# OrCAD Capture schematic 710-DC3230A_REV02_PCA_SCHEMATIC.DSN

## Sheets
1 PAGE1: size Custom
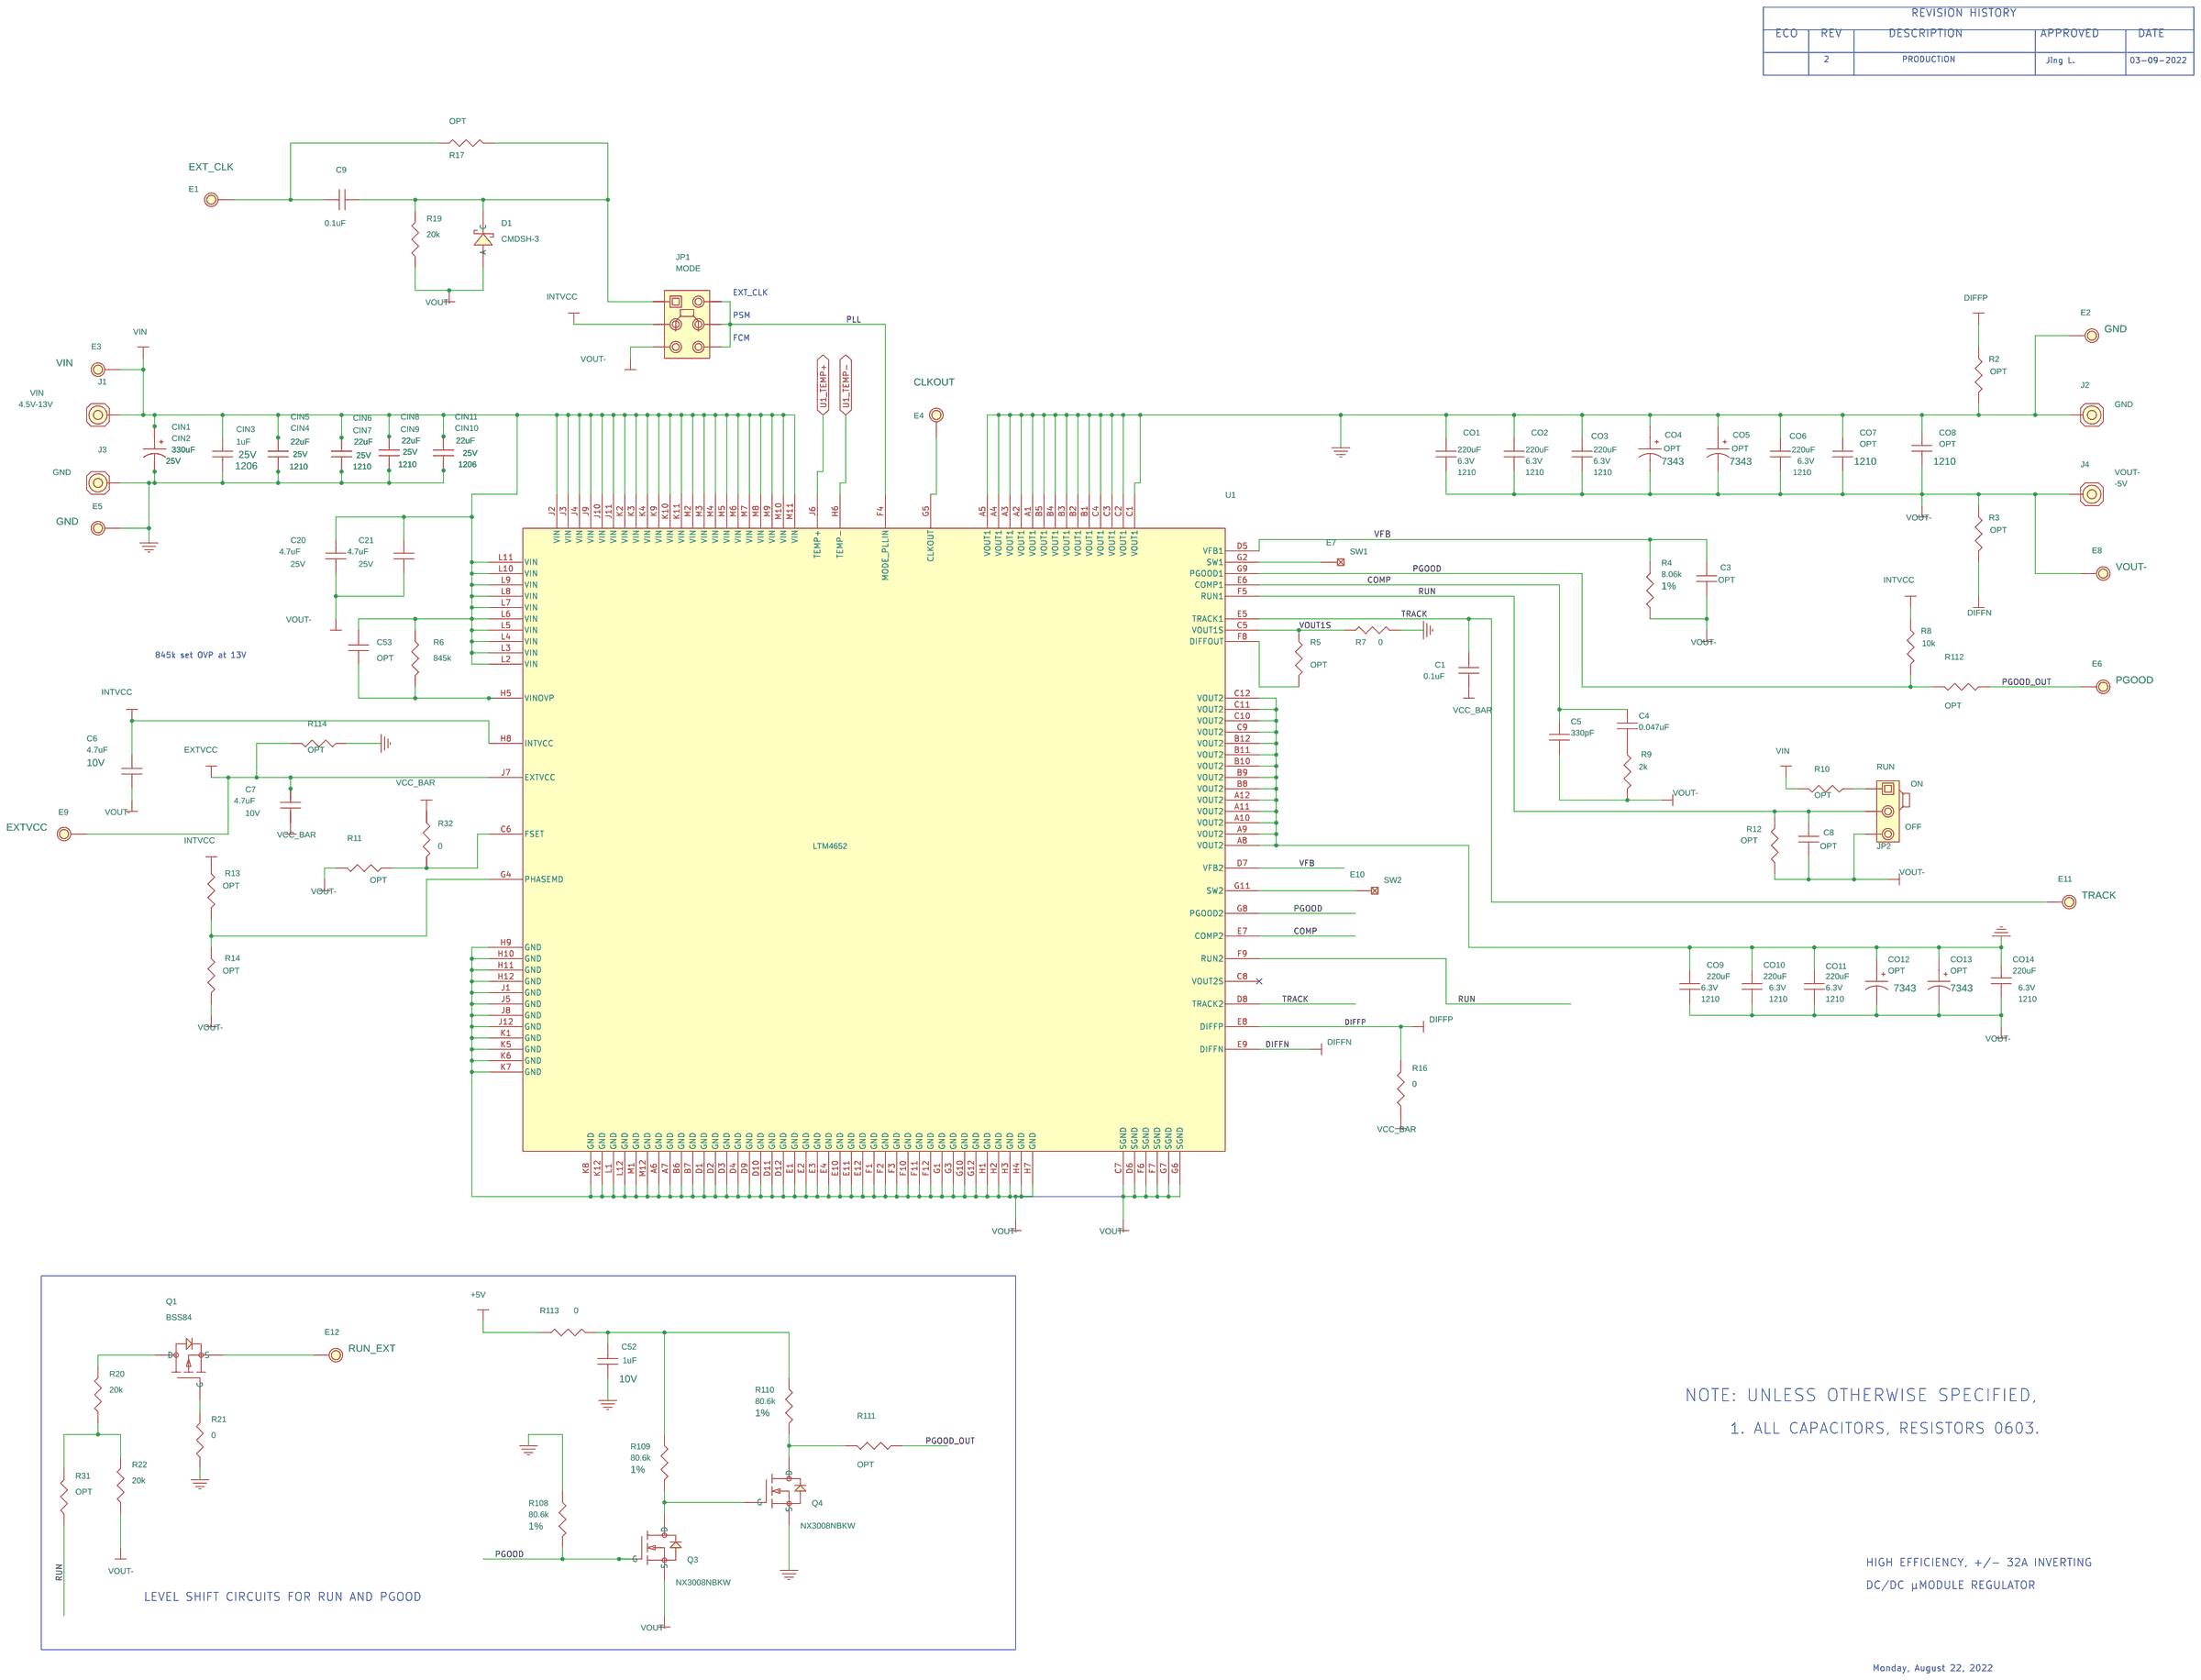
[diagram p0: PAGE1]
2 PAGE2: size Custom
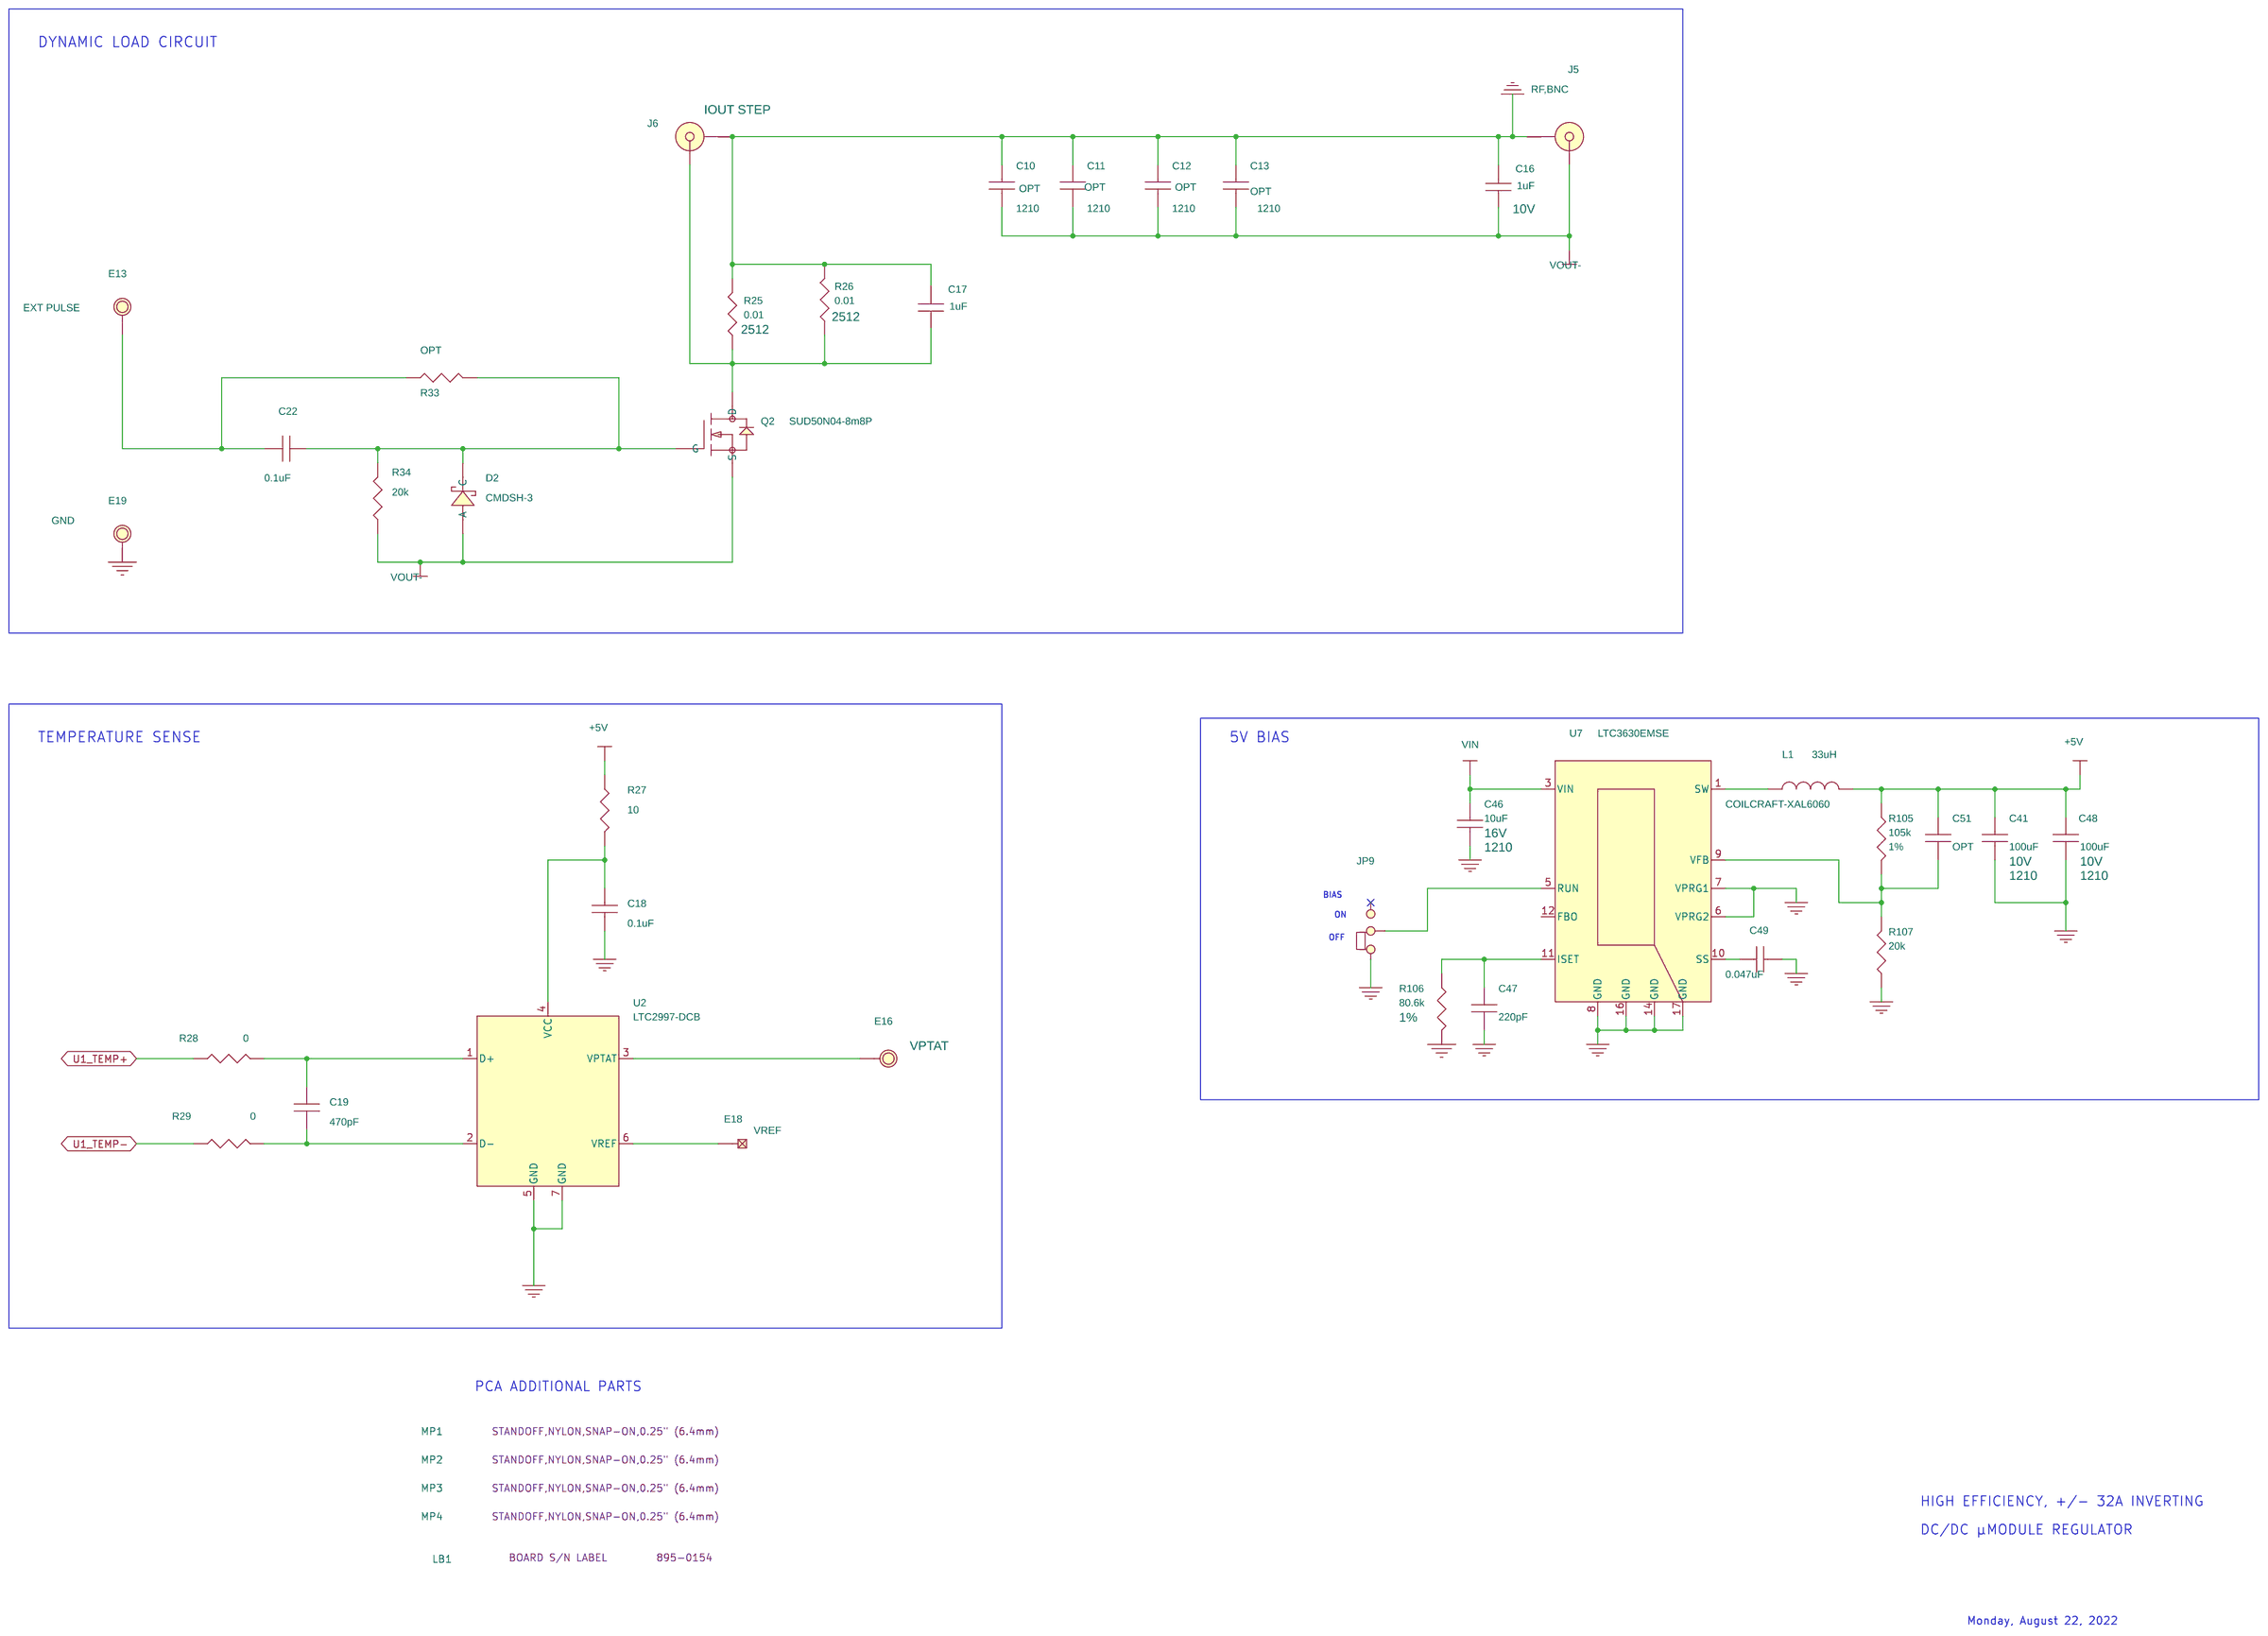
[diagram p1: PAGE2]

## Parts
sheet PAGE1
C1  0.1uF  [CC0603N]
C3  OPT  [CC0603N]
C4  0.047uF  [CC0603N]
C5  330pF  [CC0603N]
C6  4.7uF  [CC0603N]
C7  4.7uF  [CC0603N]
C8  OPT  [CC0603N]
C9  0.1uF  [CC0603N]
C20  4.7uF  [CC0603N]
C21  4.7uF  [CC0603N]
C52  1uF  [CC0603N]
C53  OPT  [CC0603N]
CIN1  330uF  [PANASONIC_ZC_10X10.2]
CIN2  330uF  [PANASONIC_ZC_10X10.2]
CIN3  1uF  [CC1206N]
CIN4  22uF  [CC1210N]
CIN5  22uF  [CC1210N]
CIN6  22uF  [CC1210N]
CIN7  22uF  [CC1210N]
CIN8  22uF  [CC1210N]
CIN9  22uF  [CC1210N]
CIN10  22uF  [CC1206N]
CIN11  22uF  [CC1206N]
CO1  220uF  [CC1210N]
CO2  220uF  [CC1210N]
CO3  220uF  [CC1210N]
CO4  OPT  [CAPMP7343N]
CO5  OPT  [CAPMP7343N]
CO6  220uF  [CC1210N]
CO7  OPT  [CC1210N]
CO8  OPT  [CC1210N]
CO9  220uF  [CC1210N]
CO10  220uF  [CC1210N]
CO11  220uF  [CC1210N]
CO12  OPT  [CAPMP7343N]
CO13  OPT  [CAPMP7343N]
CO14  220uF  [CC1210N]
D1  CMDSH-3  [SOD-323N]
E1  TEST POINT  [MILLMAX2308]
E2  TEST POINT  [MILLMAX2308]
E3  TEST POINT  [MILLMAX2308]
E4  TEST POINT  [MILLMAX2308]
E5  TEST POINT  [MILLMAX2308]
E6  TEST POINT  [MILLMAX2308]
E7  Testpoint  [030\smd]
E8  TEST POINT  [MILLMAX2308]
E9  TEST POINT  [MILLMAX2308]
E10  Testpoint  [030\smd]
E11  TEST POINT  [MILLMAX2308]
E12  TEST POINT  [MILLMAX2308]
J1  STUD,#10-32  [PENN-KFH-032]
J2  STUD,#10-32  [PENN-KFH-032]
J3  STUD,#10-32  [PENN-KFH-032]
J4  STUD,#10-32  [PENN-KFH-032]
JP1  HDR  [HD2X3-079]
JP2  HDR  [HD1X3-079]
Q1  BSS84  [SOT23-3N]
Q3  NX3008NBKW  [SOT323-3N]
Q4  NX3008NBKW  [SOT323-3N]
R2  OPT  [CR0603N]
R3  OPT  [CR0603N]
R4  8.06k  [CR0603N]
R5  OPT  [CR0603N]
R6  845k  [CR0603N]
R7  0  [CR0603N]
R8  10k  [CR0603N]
R9  2k  [CR0603N]
R10  OPT  [CR0603N]
R11  OPT  [CR0603N]
R12  OPT  [CR0603N]
R13  OPT  [CR0603N]
R14  OPT  [CR0603N]
R16  0  [CR0603N]
R17  OPT  [CR0603N]
R19  20k  [CR0603N]
R20  20k  [CR0603N]
R21  0  [CR0603N]
R22  20k  [CR0603N]
R31  OPT  [CR0603N]
R32  0  [CR0603N]
R108  80.6k  [CR0603N]
R109  80.6k  [CR0603N]
R110  80.6k  [CR0603N]
R111  OPT  [CR0603N]
R112  OPT  [CR0603N]
R113  0  [CR0603N]
R114  OPT  [CR0603N]
U1  LTM4652  [LTM-BGA-144-7064]
XJP1  SHUNT
XJP2  SHUNT
sheet PAGE2
C10  OPT  [CC1210N]
C11  OPT  [CC1210N]
C12  OPT  [CC1210N]
C13  OPT  [CC1210N]
C16  1uF  [CC0603N]
C17  1uF  [CC0603N]
C18  0.1uF  [CC0603N]
C19  470pF  [CC0603N]
C22  0.1uF  [CC0603N]
C41  100uF  [CC1210N]
C46  10uF  [CC1210N]
C47  220pF  [CC0603N]
C48  100uF  [CC1210N]
C49  0.047uF  [CC0603N]
C51  OPT  [CC0603N]
D2  CMDSH-3  [SOD-323N]
E13  TEST POINT  [MILLMAX2308]
E16  TEST POINT  [MILLMAX2308]
E18  Testpoint  [030\smd]
E19  TEST POINT  [MILLMAX2308]
J5  RF,BNC  [CONNEX-112404]
J6  RF,BNC  [CONNEX-112404]
JP9  HDR  [HD1X3-079]
L1  33uH  [COILCRAFT-XAL6060]
LB1  LABEL  [895-0154_REV01]
MP1  STANDOFF  [MTG-8831]
MP2  STANDOFF  [MTG-8831]
MP3  STANDOFF  [MTG-8831]
MP4  STANDOFF  [MTG-8831]
Q2  SUD50N04-8m8P  [TO-252-3N]
R25  0.01  [VISHAY-WSL2512_T30]
R26  0.01  [VISHAY-WSL2512_T30]
R27  10  [CR0603N]
R28  0  [CR0603N]
R29  0  [CR0603N]
R33  OPT  [CR0603N]
R34  20k  [CR0603N]
R105  105k  [CR0603N]
R106  80.6k  [CR0603N]
R107  20k  [CR0603N]
U2  LTC2997-DCB  [LTC-DCB-6-1715]
U7  LTC3630EMSE  [LTC-MSE-16-1871]
XJP9  SHUNT

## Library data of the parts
C1 C9 C22 = CAP: CAP.,0.1uF,X7R,25V,10%,0603; CLASS: DISCRETE; Dielectric Type: X7R; FPLIST: CC0603N,CC0603L,CC0603M; Inventory Qty: 60590; Manufacturer: AVX; Manufacturer PN: 06033C104KAT2A; PART_NUMBER: 150-0065; Package Size: 0603; Part Number: AVX 06033C104KAT2A; Rated Voltage: 25V; Tolerance: 10%
C3 C8 C53 = CAP: CAP., OPTION, 0603; 6th Part Field: (OPT); CLASS: DISCRETE; FPLIST: CC0603N,CC0603L,CC0603M; PART_NUMBER: 150-3038; Package Size: 0603; Package Type: SMD; Part Number: OPTION
C4 = CAP: CAP.,0.047uF,X7R,50V,10%,0603; 6th Part Field: 10nF; CLASS: DISCRETE; Dielectric Type: X7R; FPLIST: CC0603N,CC0603L,CC0603M; Inventory Qty: 19580; Manufacturer: AVX; Manufacturer PN: 06035C473KAT2A; PART_NUMBER: 150-0097; Package Size: 0603; Part Number: OPTION; Rated Voltage: 50V; Tolerance: 10%
C5 = CAP: CAP.,330pF,C0G,50V,5%,0603; 6th Part Field: (OPT); CLASS: DISCRETE; Dielectric Type: C0G; FPLIST: CC0603N,CC0603L,CC0603M; Inventory Qty: 11392; Manufacturer: AVX; Manufacturer PN: 06035A331JAT2A; PART_NUMBER: 150-0611; Package Size: 0603; Part Number: OPTION; Rated Voltage: 50V; Tolerance: 5%
C6 = CAP: CAP.,4.7uF,X5R,10V,10%,0603; 1st Part Field: 10V; CLASS: DISCRETE; Dielectric Type: X5R; FPLIST: CC0603N,CC0603L,CC0603M; Inventory Qty: 20774; Manufacturer: AVX; Manufacturer PN: 0603ZD475KAT2A; PART_NUMBER: 150-3050; Package Size: 0603; Part Number: TAIYO YUDEN LMK107BJ225MA; Rated Voltage: 10V; Tolerance: 10%
C7 = CAP: CAP.,4.7uF,X5R,10V,20%,0603; 1st Part Field: 10V; CLASS: DISCRETE; Dielectric Type: X5R; FPLIST: CC0603N,CC0603L,CC0603M; Inventory Qty: 700; Manufacturer: WURTH ELEKTRONIK; Manufacturer PN: 885012106012; PART_NUMBER: 150-0743; Package Size: 0603; Part Number: TAIYO YUDEN LMK107BJ225MA; Rated Voltage: 10V; Tolerance: 20%
C20 C21 = CAP: CAP.,4.7uF,X5R,25V,10%,0603; 1st Part Field: 10V; CLASS: DISCRETE; Dielectric Type: X5R; FPLIST: CC0603N,CC0603L,CC0603M; Inventory Qty: 10846; Manufacturer: MURATA; Manufacturer PN: GRM188R61E475KE15D; PART_NUMBER: 150-0445; Package Size: 0603; Part Number: TAIYO YUDEN LMK107BJ225MA; Rated Voltage: 25V; Tolerance: 10%
C16 C17 C52 = CAP: CAP.,1uF,X7R,10V,10%,0603; CLASS: DISCRETE; Dielectric Type: X7R; FPLIST: CC0603N,CC0603L,CC0603M; Inventory Qty: 56548; Manufacturer: AVX; Manufacturer PN: 0603ZC105KAT2A; PART_NUMBER: 150-3414; Package Size: 0603; Rated Voltage: 10V; Tolerance: 10%
CIN1 CIN2 = CAP_P_ALT: CAP.,330uF,ALUM POLYMER ELEC,25V,20%,SMD,10x10.2mm,AEC-Q200; 1st Part Field: 25V; CLASS: DISCRETE; Dielectric Type: ALUM POLYMER ELEC; FPLIST: PANASONIC_ZC_10X10.2,PANASONIC_ZC_10X10-2; Inventory Qty: 1970; Manufacturer: PANASONIC; Manufacturer PN: EEHZC1E331P; PART_NUMBER: 150-1278; Package Size: SMD,10x10.2mm; Part Number: SUNCON 25CE150AX; Rated Voltage: 25V; Tolerance: 20%
CIN3 = CAP: CAP.,1uF,X7R,25V,10%,1206; 1st Part Field: 25V; CLASS: DISCRETE; Dielectric Type: X7R; FPLIST: CC1206N,CC1206L,CC1206M; Inventory Qty: 22532; Manufacturer: AVX; Manufacturer PN: 12063C105KAT2A; PART_NUMBER: 150-0174; Package Size: 1206; Part Number: TAIYO YUDEN TMK316BJ105KD-T; Rated Voltage: 25V; Tolerance: 10%
CIN4-CIN9 = CAP: CAP.,22uF,X5R,25V,10%,1210,NO SUBS ALLOWED; 1st Part Field: 25V; CLASS: DISCRETE; Dielectric Type: X5R; FPLIST: CC1210N,CC1210L,CC1210M; Inventory Qty: 4000; Manufacturer: MURATA; Manufacturer PN: GRM32ER61E226KE15K; PART_NUMBER: 150-1818; Package Size: 1210; Package Type: SMD; Part Number: AVX 1210D226KAT2A; Rated Voltage: 25V; Tolerance: 10%
CIN10 CIN11 = CAP: CAP.,22uF,X6S,25V,20%,1206; 1st Part Field: 25V; CLASS: DISCRETE; Dielectric Type: X6S; FPLIST: CC1206N,CC1206L,CC1206M; Inventory Qty: 0; Manufacturer: MURATA; Manufacturer PN: GRM31CC81E226ME11L; PART_NUMBER: 150-1811; Package Size: 1206; Part Number: AVX 1210D226KAT2A; Rated Voltage: 25V; Tolerance: 20%
CO1-CO3 CO6 CO10 CO11 CO14 = CAP: CAP.,220uF,X5R,6.3V,20%,1210,NO SUBS ALLOWED; 6th Part Field: (OPT); CLASS: DISCRETE; Dielectric Type: X5R; FPLIST: CC1210L,CC1210N,CC1210M; Inventory Qty: 4000; Manufacturer: MURATA; Manufacturer PN: GRM32ER60J227ME05K; PART_NUMBER: 150-1822; Package Size: 1210; Package Type: Surface Mount, MLCC; Part Number: OPTION; Rated Voltage: 6.3V; Temperature Coefficient: X5R; Tolerance: 20%
CO4 CO5 CO12 CO13 = CAP_P_ALT: CAP., OPTION, 7343; CLASS: DISCRETE; FPLIST: CAPMP7343N,CAPMP7343L,CAPMP7343M; PART_NUMBER: 150-0067; Package Size: 7343; Package Type: SMD; Part Number: SANYO 4TPE470MCL
CO7 CO8 = CAP: CAP., OPTION, 1210; 1st Part Field: 6.3V; CLASS: DISCRETE; FPLIST: CC1210N,CC1210L,CC1210M; PART_NUMBER: 150-3035; Package Size: 1210; Package Type: SMD; Part Number: TAIYO YUDEN LMK325BJ107MM-T
CO9 = CAP: CAP.,220uF,X5R,6.3V,20%,1210,NO SUBS ALLOWED; 1st Part Field: 6.3V; CLASS: DISCRETE; Dielectric Type: X5R; FPLIST: CC1210L,CC1210N,CC1210M; Inventory Qty: 4000; Manufacturer: MURATA; Manufacturer PN: GRM32ER60J227ME05K; PART_NUMBER: 150-1822; Package Size: 1210; Package Type: Surface Mount, MLCC; Part Number: TAIYO YUDEN LMK325BJ107MM-T; Rated Voltage: 6.3V; Temperature Coefficient: X5R; Tolerance: 20%
D1 D2 = DIODE_SCHOTTKY_A: DIODE,SCHOTTKY,30V,250mW, 100mA,SOD-323; CLASS: DISCRETE; FPLIST: SOD-323N,SOD-323L,SOD-323M; Inventory Qty: 7578; Manufacturer: CENTRAL SEMI.; Manufacturer PN: CMDSH-3 TR LEAD FREE; Max Forward Current or Rated Power: 100mA; PART_NUMBER: 210-0081; Package Size: SOD-323; Package Type: SOD-323; Rated Voltage or Zener Voltage: 30V
E1 = TEST_POINT_.156_MILL-MAX_2308_A: TEST POINT,TURRET,0.064" MTG. HOLE,PCB 0.062" THK; CLASS: IO; Inventory Qty: 1142083; Manufacturer: MILL-MAX; Manufacturer PN: 2308-2-00-80-00-00-07-0; PART_FIELD_1: EXT_CLK; PART_NUMBER: 260-0004
E2 E5 E19 = TEST_POINT_.156_MILL-MAX_2308_A: TEST POINT,TURRET,0.064" MTG. HOLE,PCB 0.062" THK; CLASS: IO; Inventory Qty: 1142083; Manufacturer: MILL-MAX; Manufacturer PN: 2308-2-00-80-00-00-07-0; PART_FIELD_1: GND; PART_NUMBER: 260-0004
E3 = TEST_POINT_.156_MILL-MAX_2308_A: TEST POINT,TURRET,0.064" MTG. HOLE,PCB 0.062" THK; CLASS: IO; Inventory Qty: 1142083; Manufacturer: MILL-MAX; Manufacturer PN: 2308-2-00-80-00-00-07-0; PART_FIELD_1: VIN; PART_NUMBER: 260-0004
E4 = TEST_POINT_.156_MILL-MAX_2308_A: TEST POINT,TURRET,0.064" MTG. HOLE,PCB 0.062" THK; CLASS: IO; Inventory Qty: 1142083; Manufacturer: MILL-MAX; Manufacturer PN: 2308-2-00-80-00-00-07-0; PART_FIELD_1: CLKOUT; PART_NUMBER: 260-0004
E6 = TEST_POINT_.156_MILL-MAX_2308_A: TEST POINT,TURRET,0.064" MTG. HOLE,PCB 0.062" THK; CLASS: IO; Inventory Qty: 1142083; Manufacturer: MILL-MAX; Manufacturer PN: 2308-2-00-80-00-00-07-0; PART_FIELD_1: PGOOD; PART_NUMBER: 260-0004
E7 = Testpad_075_smd_0: PAD; 9th Part Field: SW1; Part Number: PAD
E8 = TEST_POINT_.156_MILL-MAX_2308_A: TEST POINT,TURRET,0.064" MTG. HOLE,PCB 0.062" THK; CLASS: IO; Inventory Qty: 1142083; Manufacturer: MILL-MAX; Manufacturer PN: 2308-2-00-80-00-00-07-0; PART_FIELD_1: VOUT-; PART_NUMBER: 260-0004
E9 = TEST_POINT_.156_MILL-MAX_2308_A: TEST POINT,TURRET,0.064" MTG. HOLE,PCB 0.062" THK; CLASS: IO; Inventory Qty: 1142083; Manufacturer: MILL-MAX; Manufacturer PN: 2308-2-00-80-00-00-07-0; PART_FIELD_1: EXTVCC; PART_NUMBER: 260-0004
E10 = Testpad_075_smd_0: PAD; 9th Part Field: SW2; Part Number: PAD
E11 = TEST_POINT_.156_MILL-MAX_2308_A: TEST POINT,TURRET,0.064" MTG. HOLE,PCB 0.062" THK; CLASS: IO; Inventory Qty: 1142083; Manufacturer: MILL-MAX; Manufacturer PN: 2308-2-00-80-00-00-07-0; PART_FIELD_1: TRACK; PART_NUMBER: 260-0004
E12 = TEST_POINT_.156_MILL-MAX_2308_A: TEST POINT,TURRET,0.064" MTG. HOLE,PCB 0.062" THK; CLASS: IO; Inventory Qty: 1142083; Manufacturer: MILL-MAX; Manufacturer PN: 2308-2-00-80-00-00-07-0; PART_FIELD_1: RUN_EXT; PART_NUMBER: 260-0004
J1 = PEM-KFH: EVAL BOARD STUD HARDWARE SET, #10-32-INACTIVE PART; 10th Part Field: 4.5V-13V; 9th Part Field: VIN; CLASS: DISCRETE; Comments: CONSISTS OF QTY(1) STUD, 769-0012; QTY(1) RING LUG, 769-0013;QTY(2) HEX NUT,BRASS,761-0013; QTY(1) WASHER,#10 LOCK, 762-0021; Manufacturer: ANALOG DEVICES; Manufacturer PN: 720-0010; PART_NUMBER: 720-0010
J2 = PEM-KFH: EVAL BOARD STUD HARDWARE SET, #10-32-INACTIVE PART; 10th Part Field: -5V; 9th Part Field: VOUT-; CLASS: DISCRETE; Comments: CONSISTS OF QTY(1) STUD, 769-0012; QTY(1) RING LUG, 769-0013;QTY(2) HEX NUT,BRASS,761-0013; QTY(1) WASHER,#10 LOCK, 762-0021; Manufacturer: ANALOG DEVICES; Manufacturer PN: 720-0010; PART_NUMBER: 720-0010
J3 J4 = PEM-KFH: EVAL BOARD STUD HARDWARE SET, #10-32-INACTIVE PART; 9th Part Field: GND; CLASS: DISCRETE; Comments: CONSISTS OF QTY(1) STUD, 769-0012; QTY(1) RING LUG, 769-0013;QTY(2) HEX NUT,BRASS,761-0013; QTY(1) WASHER,#10 LOCK, 762-0021; Manufacturer: ANALOG DEVICES; Manufacturer PN: 720-0010; PART_NUMBER: 720-0010
JP1 = HDR2X3_ALT1: CONN.,HDR,MALE,2x3,2mm,VERT,ST,THT; 9th Part Field: MODE; CLASS: IO; Inventory Qty: 17651; Manufacturer: WURTH ELEKTRONIK; Manufacturer PN: 62000621121; PART_NUMBER: 250-0483
JP2 = 1X3_A: CONN.,HDR,MALE,1x3,2mm,VERT,ST,THT,NO SUBS. ALLOWED; 11th Part Field: OFF; 12th Part Field: RUN; 9th Part Field: ON; CLASS: IO; Inventory Qty: 28997; Manufacturer: Wurth Elektronik; Manufacturer PN: 62000311121; PART_NUMBER: 250-0639
Q1 = 3P_P-CH_TYPE1A: XSTR.,MOSFET, P-CH,50V,0.13A,SOT23-3; CLASS: DISCRETE; FPLIST: SOT23-3N,SOT23-3L,SOT23-3M; Inventory Qty: 3480; Manufacturer: FAIRCHILD SEMI; PART_NUMBER: 240-0231; Package Size: TO-236-3, SC-59, SOT-23-3; Package Type: SOT23-3; Polarity: MOSFET P-Channel, Metal Oxide; Rated Power: 360mW; Rated Voltage: 50V
Q3 Q4 = 3P_N-CH_TYPE1A: XSTR.,MOSFET N-CH,30V,350mA,SOT-323; CLASS: DISCRETE; Inventory Qty: 0; Manufacturer: NEXPERIA; Manufacturer PN: NX3008NBKW,115; PART_NUMBER: 240-0626; Package Size: SC-70, SOT-323; Package Type: SOT-323; Rated Power: 260mW (Ta), 830mW (Tc); Rated Voltage: 30V
R2 R3 = RES: RES., OPTION, 0603; CLASS: DISCRETE; FPLIST: CR0603N,CR0603L,CR0603M; PART_NUMBER: 100-2374; Package Size: 0603; Part Number: VISHAY CRCW060310R0JNEA
R4 = RES: RES.,8.06k OHMS,1%,1/10W,0603; 5th Part Field: CCRCW060330K1FKEA; CLASS: DISCRETE; FPLIST: CR0603N,CR0603L,CR0603M; Inventory Qty: 18284; Manufacturer: YAGEO; Manufacturer PN: RC0603FR-078K06L; PART_NUMBER: 100-0161; Package Size: 0603; Part Number: VISHAY CCRCW060330K1FKEA; Rated Power: 1/10W; Temperature Coefficient: 100ppm/C; Tolerance: 1%
R5 R11 R31 R111 R112 = RES: RES., OPTION, 0603; CLASS: DISCRETE; FPLIST: CR0603N,CR0603L,CR0603M; PART_NUMBER: 100-2374; Package Size: 0603; Part Number: VISHAY CRCW06030000Z0EA
R6 = RES: RES.,845k OHMS,1%,1/10W,0603,AEC-Q200; CLASS: DISCRETE; FPLIST: CR0603N,CR0603L,CR0603M; Inventory Qty: 11170; Manufacturer: VISHAY; Manufacturer PN: CRCW0603845KFKEA; PART_NUMBER: 100-2504; Package Size: 0603; Rated Power: 1/10W; Temperature Coefficient: 100ppm/C; Tolerance: 1%
R7 = RES: RES.,0 OHM,1/10W,0603,AEC-Q200; 6th Part Field: (OPT); CLASS: DISCRETE; FPLIST: CR0603N,CR0603L,CR0603M; Inventory Qty: 60662; Manufacturer: PANASONIC; Manufacturer PN: ERJ3GEY0R00V; PART_NUMBER: 100-0204; Package Size: 0603; Part Number: OPTION; Rated Power: 1/10W
R8 = RES: RES.,10k OHMS,5%,1/10W,0603,AEC-Q200; CLASS: DISCRETE; FPLIST: CR0603N,CR0603L,CR0603M; Inventory Qty: 58588; Manufacturer: NIC; Manufacturer PN: NRC06J103TRF; PART_NUMBER: 100-2013; Package Size: 0603; Part Number: VISHAY CRCW060310K0JNEA; Rated Power: 1/10W; Temperature Coefficient: 200ppm/C; Tolerance: 5%
R9 = RES: RES.,2k OHMS,1%,1/10W,0603; 6th Part Field: 2.32K; CLASS: DISCRETE; FPLIST: CR0603N,CR0603L,CR0603M; Inventory Qty: 48241; Manufacturer: NIC; Manufacturer PN: NRC06F2001TRF; PART_NUMBER: 100-2313; Package Size: 0603; Part Number: OPTION; Rated Power: 1/10W; Temperature Coefficient: 100ppm/C; Tolerance: 1%
R10 R12-R14 R17 R33 R114 = RES: RES., OPTION, 0603; 6th Part Field: (OPT); CLASS: DISCRETE; FPLIST: CR0603N,CR0603L,CR0603M; PART_NUMBER: 100-2374; Package Size: 0603; Part Number: OPTION
R16 R113 = RES: RES.,0 OHM,1/10W,0603,AEC-Q200; CLASS: DISCRETE; FPLIST: CR0603N,CR0603L,CR0603M; Inventory Qty: 60662; Manufacturer: PANASONIC; Manufacturer PN: ERJ3GEY0R00V; PART_NUMBER: 100-0204; Package Size: 0603; Part Number: VISHAY CRCW06030000Z0EA; Rated Power: 1/10W
R19 R34 = RES: RES.,20k OHMS,1%,1/10W,0603; CLASS: DISCRETE; FPLIST: CR0603N,CR0603L,CR0603M; Inventory Qty: 145296; Manufacturer: NIC; Manufacturer PN: NRC06F2002TRF; PART_NUMBER: 100-2117; Package Size: 0603; Part Number: VISHAY CRCW06030000Z0EA; Rated Power: 1/10W; Temperature Coefficient: +/-100PPM; Tolerance: 1%
R20 R22 = RES: RES.,20k OHMS,5%,1/10W,0603,AEC-Q200; CLASS: DISCRETE; FPLIST: CR0603N,CR0603L,CR0603M; Inventory Qty: 36503; Manufacturer: NIC; Manufacturer PN: NRC06J203TRF; PART_NUMBER: 100-0160; Package Size: 0603; Part Number: VISHAY CRCW06030000Z0EA; Rated Power: 1/10W; Temperature Coefficient: 200ppm/C; Tolerance: 5%
R21 R32 = RES: RES.,0 OHM,1/10W,0603,AEC-Q200; CLASS: DISCRETE; FPLIST: CR0603N,CR0603L,CR0603M; Inventory Qty: 676258; Manufacturer: VISHAY; Manufacturer PN: CRCW06030000Z0EA; PART_NUMBER: 100-0009; Package Size: 0603; Part Number: VISHAY CRCW06030000Z0EA; Rated Power: 1/10W
R106 R108-R110 = RES: RES.,80.6k OHMS,1%,1/10W,0603; 1ST PART FIELD: 1%; CLASS: DISCRETE; FPLIST: CR0603N,CR0603L,CR0603M; Inventory Qty: 56958; Manufacturer: VISHAY; Manufacturer PN: CRCW060380K6FKEA; PART_NUMBER: 100-2503; Package Size: 0603; Rated Power: 1/10W; Temperature Coefficient: 100ppm/C; Tolerance: 1%
U1 = LTM4652: IC,BiDR uModule Reg Dual +/-25A,or Single +/-50A DC/DC,PRELIM; CLASS: IC; Inventory Qty: 0; Manufacturer: ANALOG DEVICES; Manufacturer PN: LTM4652EY#PBF; PART_NUMBER: LTM4652EY#PBF; Package Size: 16mmX16mmX4.92mm
XJP1 XJP2 = SHUNT_2MM: CONN.,SHUNT,FEMALE,2-POS,2mm; CLASS: IO; Inventory Qty: 64675; Manufacturer: Wurth Elektronik; Manufacturer PN: 60800213421; PART_NUMBER: 250-0485
C10-C13 = CAP: CAP., OPTION, 1210; CLASS: DISCRETE; FPLIST: CC1210N,CC1210L,CC1210M; PART_NUMBER: 150-3035; Package Size: 1210; Package Type: SMD
C18 = CAP: CAP.,0.1uF,X7R,25V,10%,0603; CLASS: DISCRETE; Dielectric Type: X7R; FPLIST: CC0603N,CC0603L,CC0603M; Inventory Qty: 60590; Manufacturer: AVX; Manufacturer PN: 06033C104KAT2A; PART_NUMBER: 150-0065; Package Size: 0603; Rated Voltage: 25V; Tolerance: 10%
C19 = CAP: CAP.,470pF,X7R,50V,10%,0603; CLASS: DISCRETE; Dielectric Type: X7R; FPLIST: CC0603N,CC0603L,CC0603M; Inventory Qty: 33012; Manufacturer: AVX; Manufacturer PN: 06035C471KAT2A; PART_NUMBER: 150-0125; Package Size: 0603; Rated Voltage: 50V; Tolerance: 10%
C41 C48 = CAP: CAP.,100uF,X5R,10V,20%,1210; CLASS: DISCRETE; Dielectric Type: X5R; FPLIST: CC1210N,CC1210L,CC1210M; Inventory Qty: 19694; Manufacturer: KEMET; Manufacturer PN: C1210C107M8PACTU; PART_NUMBER: 150-3234; Package Size: 1210; Rated Voltage: 10V; Tolerance: 20%
C46 = CAP: CAP.,10uF,X5R,16V,20%,1210; CLASS: DISCRETE; Dielectric Type: X5R; FPLIST: CC1210N,CC1210L,CC1210M; Inventory Qty: 4766; Manufacturer: AVX; Manufacturer PN: 1210YD106MAT2A; PART_NUMBER: 150-0099; Package Size: 1210; Rated Voltage: 16V; Tolerance: 20%
C47 = CAP: CAP.,220pF,X7R,50V,10%,0603; CLASS: DISCRETE; Dielectric Type: X7R; FPLIST: CC0603N,CC0603L,CC0603M; Inventory Qty: 35058; Manufacturer: AVX; Manufacturer PN: 06035C221KAT2A; PART_NUMBER: 150-0062; Package Size: 0603; Rated Voltage: 50V; Tolerance: 10%
C49 = CAP: CAP.,0.047uF,X7R,50V,10%,0603; CLASS: DISCRETE; Dielectric Type: X7R; FPLIST: CC0603N,CC0603L,CC0603M; Inventory Qty: 19580; Manufacturer: AVX; Manufacturer PN: 06035C473KAT2A; PART_NUMBER: 150-0097; Package Size: 0603; Rated Voltage: 50V; Tolerance: 10%
C51 = CAP: CAP., OPTION, 0603; CLASS: DISCRETE; FPLIST: CC0603N,CC0603L,CC0603M; PART_NUMBER: 150-3038; Package Size: 0603; Package Type: SMD
E13 = TEST_POINT_.156_MILL-MAX_2308_A: TEST POINT,TURRET,0.064" MTG. HOLE,PCB 0.062" THK; CLASS: IO; Inventory Qty: 1142083; Manufacturer: MILL-MAX; Manufacturer PN: 2308-2-00-80-00-00-07-0; PART_FIELD_1: EXT PULSE; PART_NUMBER: 260-0004
E16 = TEST_POINT_.156_MILL-MAX_2308_A: TEST POINT,TURRET,0.064" MTG. HOLE,PCB 0.062" THK; CLASS: IO; Inventory Qty: 1142083; Manufacturer: MILL-MAX; Manufacturer PN: 2308-2-00-80-00-00-07-0; PART_FIELD_1: VPTAT; PART_NUMBER: 260-0004
E18 = Testpad_075_smd_0: PAD; 9th Part Field: VREF; Part Number: PAD
J5 = BNC_50_OHM_112404_B_2: CONN.,RF,BNC,RCPT,JACK,5-PIN,ST,THT,50 OHMS; CLASS: IO; Inventory Qty: 80023; Manufacturer: AMPHENOL RF; Manufacturer PN: 112404; PART_FIELD_01: VOUT; PART_NUMBER: 250-0427
J6 = BNC_50_OHM_112404_B: CONN.,RF,BNC,RCPT,JACK,5-PIN,ST,THT,50 OHMS; CLASS: IO; Inventory Qty: 80023; Manufacturer: AMPHENOL RF; Manufacturer PN: 112404; PART_FIELD_01: IOUT STEP; PART_NUMBER: 250-0427
JP9 = 1X3_F: CONN.,HDR,MALE,1x3,2mm,VERT,ST,THT,NO SUBS. ALLOWED; CLASS: IO; Inventory Qty: 28997; Manufacturer: Wurth Elektronik; Manufacturer PN: 62000311121; PART_NUMBER: 250-0639
L1 = IND_ALT: IND.,33uH,PWR,SHIELDED,20%,3.6A,105mOHMS,6.56x6.36mm,AEC-Q200,XAL6060; CLASS: DISCRETE; Inventory Qty: 0; Manufacturer: COILCRAFT; Manufacturer PN: XAL6060-333MEB; PART_NUMBER: 200-0679; Package Size: 6.56x6.36mm; Tolerance: 20%
LB1 = BLANK_LABEL: LABEL SPEC, DEMO BOARD SERIAL NUMBER; Inventory Qty: 0; Manufacturer: BRADY; Manufacturer PN: THT-96-717-10; PART_FIELD_01: BOARD S/N LABEL; PART_NUMBER: 895-0154
MP1-MP4 = BLANK_MECHANICAL_PART: STANDOFF,NYLON,SNAP-ON,0.25" (6.4mm); CLASS: DISCRETE; Inventory Qty: 227624; Manufacturer: KEYSTONE; Manufacturer PN: 8831; PART_NUMBER: 763-0006
Q2 = 3P_N-CH_TYPE2A: XSTR.,MOSFET,N-CH,40V,14A,DPAK (TO-252); CLASS: DISCRETE; FPLIST: TO-252-3N,TO-252-3L,TO-252-3M; Inventory Qty: 44191; Manufacturer: VISHAY; Manufacturer PN: SUD50N04-8M8P-4GE3; PART_NUMBER: 240-0021; Package Type: DPAK (TO-252); Rated Voltage: 40V
R25 R26 = RES: RES.,0.01 OHM,1%,1W,2512,PWR,METAL,SENSE,AEC-Q200; CLASS: DISCRETE; FPLIST: CR2512N,CR2512L,CR2512M; Inventory Qty: 18659; Label: 1W; Manufacturer: VISHAY; Manufacturer PN: WSL2512R0100FEA; PART_NUMBER: 100-0616; Package Size: 2512; Rated Power: 1W; Temperature Coefficient: 75ppm; Tolerance: 1%
R27 = RES: RES.,10 OHMS,1%,1/10W,0603; CLASS: DISCRETE; FPLIST: CR0603N,CR0603L,CR0603M; Inventory Qty: 152750; Manufacturer: VISHAY; Manufacturer PN: CRCW060310R0FKEA; PART_NUMBER: 100-2306; Package Size: 0603; Rated Power: 1/10W; Temperature Coefficient: 100ppm/C; Tolerance: 1%
R28 R29 = RES: RES.,0 OHM,1/10W,0603,AEC-Q200; CLASS: DISCRETE; FPLIST: CR0603N,CR0603L,CR0603M; Inventory Qty: 676258; Manufacturer: VISHAY; Manufacturer PN: CRCW06030000Z0EA; PART_NUMBER: 100-0009; Package Size: 0603; Rated Power: 1/10W
R105 = RES: RES.,105k OHMS,1%,1/10W,0603,AEC-Q200; CLASS: DISCRETE; FPLIST: CR0603N,CR0603L,CR0603M; Inventory Qty: 49432; Manufacturer: VISHAY; Manufacturer PN: CRCW0603105KFKEA; PART_NUMBER: 100-0366; Package Size: 0603; Rated Power: 1/10W; Temperature Coefficient: 100ppm; Tolerance: 1%
R107 = RES: RES.,20k OHMS,5%,1/10W,0603,AEC-Q200; CLASS: DISCRETE; FPLIST: CR0603N,CR0603L,CR0603M; Inventory Qty: 36503; Manufacturer: NIC; Manufacturer PN: NRC06J203TRF; PART_NUMBER: 100-0160; Package Size: 0603; Rated Power: 1/10W; Temperature Coefficient: 200ppm/C; Tolerance: 5%
U2 = LTC2997-DCB: IC,Remote Internal Temp Sensor,6-pin DFN 2mm X 3mm; CLASS: IC; Inventory Qty: 20; Manufacturer: LINEAR TECH.; Manufacturer PN: LTC2997IDCB#TRMPBF; PART_NUMBER: LTC2997IDCB#TRMPBF; Package Size: 6-WFDFN Exposed Pad; Package Type: 6-pin DFN 2mm X 3mm
U7 = LTC3630-MSE: IC,Synchr. Step-Down Converter,MSOP-16; CLASS: IC; Inventory Qty: 250; Manufacturer: ANALOG DEVICES; Manufacturer PN: LTC3630EMSE#PBF; PART_NUMBER: LTC3630EMSE#PBF; Package Type: MSOP-16 (MSE)
XJP9 = SHUNT_2MM_B: CONN.,SHUNT,FEMALE,2-POS,2mm; CLASS: IO; Inventory Qty: 64675; Manufacturer: Wurth Elektronik; Manufacturer PN: 60800213421; PART_NUMBER: 250-0485

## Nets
+5V: C41.1 C48.1 C51.1 L1.2 R27.1 R105.2 R113.1
GND: C10.1 C11.1 C12.1 C13.1 C16.2 C17.2 C18.2 C41.2 C46.2 C47.2 C48.2 C49.2 C52.1 CIN1.2 CIN2.2 CIN3.2 CIN4.2 CIN5.2 CIN6.2 CIN7.2 CIN8.2 CIN9.2 CIN10.2 CIN11.2 CO1.1 CO2.1 CO3.1 CO4.1 CO5.1 CO6.1 CO7.1 CO8.1 CO9.1 CO10.1 CO11.1 CO12.1 CO13.1 CO14.1 E2.1 E5.1 E19.1 J2.1 J3.1 J5.2 J5.3 J5.4 J5.5 J6.2 J6.3 J6.4 J6.5 JP9.3 Q4.2(S) R2.2 R7.2 R21.1 R25.2 R26.2 R106.2 R107.1 R108.1 R114.2 U1.A1(VOUT1) U1.A2(VOUT1) U1.A3(VOUT1) U1.A4(VOUT1) U1.A5(VOUT1) U1.A8(VOUT2) U1.A9(VOUT2) U1.A10(VOUT2) U1.A11(VOUT2) U1.A12(VOUT2) U1.B1(VOUT1) U1.B2(VOUT1) U1.B3(VOUT1) U1.B4(VOUT1) U1.B5(VOUT1) U1.B8(VOUT2) U1.B9(VOUT2) U1.B10(VOUT2) U1.B11(VOUT2) U1.B12(VOUT2) U1.C1(VOUT1) U1.C2(VOUT1) U1.C3(VOUT1) U1.C4(VOUT1) U1.C9(VOUT2) U1.C10(VOUT2) U1.C11(VOUT2) U1.C12(VOUT2) U2.5(GND) U2.7(GND) U7.6(VPRG2) U7.7(VPRG1) U7.8(GND) U7.14(GND) U7.16(GND) U7.17(GND)
VIN: C20.1 C21.1 C46.1 C53.2 CIN1.1 CIN2.1 CIN3.1 CIN4.1 CIN5.1 CIN6.1 CIN7.1 CIN8.1 CIN9.1 CIN10.1 CIN11.1 E3.1 J1.1 R6.1 R10.1 U1.J2(VIN) U1.J3(VIN) U1.J4(VIN) U1.J9(VIN) U1.J10(VIN) U1.J11(VIN) U1.K2(VIN) U1.K3(VIN) U1.K4(VIN) U1.K9(VIN) U1.K10(VIN) U1.K11(VIN) U1.L2(VIN) U1.L3(VIN) U1.L4(VIN) U1.L5(VIN) U1.L6(VIN) U1.L7(VIN) U1.L8(VIN) U1.L9(VIN) U1.L10(VIN) U1.L11(VIN) U1.M2(VIN) U1.M3(VIN) U1.M4(VIN) U1.M5(VIN) U1.M6(VIN) U1.M7(VIN) U1.M8(VIN) U1.M9(VIN) U1.M10(VIN) U1.M11(VIN) U7.3(VIN)
COMP: C4.1 C5.1 U1.E6(COMP1) U1.E7(COMP2)
EXTVCC: C7.1 E9.1 R114.1 U1.J7(EXTVCC)
INTVCC: C6.1 JP1.3 R8.1 R13.1 R32.1 U1.H8(INTVCC)
PGOOD: Q3.1(G) R8.2 R108.2 R112.2 U1.G8(PGOOD2) U1.G9(PGOOD1)
PGOOD_OUT: E6.1 R111.1 R112.1
PLL: JP1.2 JP1.4 JP1.6 U1.F4(MODE_PLLIN)
RUN: C8.1 JP2.2 R12.1 R31.1 U1.F5(RUN1) U1.F9(RUN2)
TRACK: C1.2 E11.1 U1.D8(TRACK2) U1.E5(TRACK1)
U1_TEMP+: R28.1 U1.J6(TEMP+)
U1_TEMP-: R29.1 U1.H6(TEMP-)
VFB: C3.1 R4.2 U1.D5(VFB1) U1.D7(VFB2)
VO+: R2.1 R16.2 U1.E8(DIFFP)
VO-: R3.2 U1.E9(DIFFN)
VOUT1S: R5.1 R7.1 U1.C5(VOUT1S)
VOUT-: C1.1 C3.2 C5.2 C6.2 C7.2 C8.2 C10.2 C11.2 C12.2 C13.2 C16.1 C20.2 C21.2 CO1.2 CO2.2 CO3.2 CO4.2 CO5.2 CO6.2 CO7.2 CO8.2 CO9.2 CO10.2 CO11.2 CO12.2 CO13.2 CO14.2 D1.2(A) D2.2(A) E8.1 J4.1 J5.1 JP1.5 JP2.3 Q2.3(S) Q3.2(S) R3.1 R4.1 R9.2 R11.2 R12.2 R14.2 R16.1 R19.1 R22.1 R34.1 U1.A6(GND) U1.A7(GND) U1.B6(GND) U1.B7(GND) U1.C7(SGND) U1.D1(GND) U1.D2(GND) U1.D3(GND) U1.D4(GND) U1.D6(SGND) U1.D9(GND) U1.D10(GND) U1.D11(GND) U1.D12(GND) U1.E1(GND) U1.E2(GND) U1.E3(GND) U1.E4(GND) U1.E10(GND) U1.E11(GND) U1.E12(GND) U1.F1(GND) U1.F2(GND) U1.F3(GND) U1.F6(SGND) U1.F7(SGND) U1.F10(GND) U1.F11(GND) U1.F12(GND) U1.G1(GND) U1.G3(GND) U1.G6(SGND) U1.G7(SGND) U1.G10(GND) U1.G12(GND) U1.H1(GND) U1.H2(GND) U1.H3(GND) U1.H4(GND) U1.H7(GND) U1.H9(GND) U1.H10(GND) U1.H11(GND) U1.H12(GND) U1.J1(GND) U1.J5(GND) U1.J8(GND) U1.J12(GND) U1.K1(GND) U1.K5(GND) U1.K6(GND) U1.K7(GND) U1.K8(GND) U1.K12(GND) U1.L1(GND) U1.L12(GND) U1.M1(GND) U1.M12(GND)
N17111026: R11.1 R32.2 U1.C6(FSET)
N17217105: JP2.1 R10.2
N17318533: E10.1 U1.G11(SW2)
N19457314: R13.2 R14.1 U1.G4(PHASEMD)
N20128546: C22.2 E13.1 R33.1
N20752823: E7.1 U1.G2(SW1)
N20777848: R5.2 U1.F8(DIFFOUT)
N20951537: C18.1 R27.2 U2.4(VCC)
N20951658: C19.1 R28.2 U2.1(D+)
N20951664: E16.1 U2.3(VPTAT)
N20951686: C19.2 R29.2 U2.2(D-)
N20958501: E4.1 U1.G5(CLKOUT)
N20966361: Q1.3(D) R20.2
N20966373: R20.1 R22.2 R31.2
N20966621: E12.1 Q1.2(S)
N20967183: C9.1 D1.1(C) JP1.1 R17.2 R19.2
N20978320: C9.2 E1.1 R17.1
N20982714: Q1.1(G) R21.2
N21005595: E18.1 U2.6(VREF)
N21026039: C17.1 J6.1 Q2.2(D) R25.1 R26.1
N21027120: C22.1 D2.1(C) Q2.1(G) R33.2 R34.2
N21028333: L1.1 U7.1(SW)
N21028408: C51.2 R105.1 R107.2 U7.9(VFB)
N21028420: JP9.2 U7.5(RUN)
N21028486: C47.1 R106.1 U7.11(ISET)
N21028494: C49.1 U7.10(SS)
N21029957: Q3.3(D) Q4.1(G) R109.2
N21030219: Q4.3(D) R110.2 R111.2
N21030222: C52.2 R109.1 R110.1 R113.2
N21054051: C53.1 R6.2 U1.H5(VINOVP)
N21069820: C4.2 R9.1

Not connected (* = marked no-connect by the designer): JP9 1*; U1 C8(VOUT2S)*; U7 12(FBO)

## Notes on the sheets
sheet 1
- REVISION HISTORY
- ECO
- REV
- DESCRIPTION
- APPROVED
- DATE
- 2
- PRODUCTION
- Jing L.
- 03-09-2022
- EXT_CLK
- PSM
- FCM
- 845k set OVP at 13V
- NOTE: UNLESS OTHERWISE SPECIFIED,
- 1. ALL CAPACITORS, RESISTORS 0603.
- HIGH EFFICIENCY, +/- 32A INVERTING
- DC/DC µMODULE REGULATOR
- LEVEL SHIFT CIRCUITS FOR RUN AND PGOOD
- Monday, August 22, 2022
sheet 2
- DYNAMIC LOAD CIRCUIT
- TEMPERATURE SENSE
- 5V BIAS
- BIAS
- ON
- OFF
- PCA ADDITIONAL PARTS
- HIGH EFFICIENCY, +/- 32A INVERTING
- DC/DC µMODULE REGULATOR
- Monday, August 22, 2022
